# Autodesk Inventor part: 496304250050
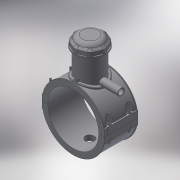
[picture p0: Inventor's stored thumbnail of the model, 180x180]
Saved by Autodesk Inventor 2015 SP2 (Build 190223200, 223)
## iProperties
Created: 2017-07
Part Number: 496304250050
Material: Generic
Description: PLASSON TAPPING SADDLE 250x50
Document SubType Name: Modeling
Designer: KIM
Mass: 1980.45 g
Surface Area: 3874.13 cm^2
Volume: 1980.45 cm^3
Density: 1 g/cm^3
Appearance: Default
Author: KIM
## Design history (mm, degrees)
derived "496304.ipt"
feature "Solid1::496304.ipt"
feature "Solid2::496304.ipt"
feature "Solid4::496304.ipt"
feature "Solid5::496304.ipt"
tag "TaggingFeature1" dims "d2" = 327.6
body "Solid1"
body "Solid2"
other parameters: "d3" = 62.5, "d4" = 176, "d5" = 0, "d6" = 0.1, "d8" = 0, "d19" = 6, "d20" = 6, "d21" = 105.6, "d23" = 0, "d24" = 52.8, "d26" = 0, "d29" = 3, "d30" = 83.33333, "d31" = 6, "d32" = 0, "d33" = 0, "d34" = 0.6, "d40" = 148.2, "d43" = 0, "d45" = 0, "d47" = 248.1, "d70" = 15, "d72" = 0, "d73" = 6, "d75" = 5, "d76" = 0, "d77" = 12.5, "d78" = 155, "d79" = 15, "d80" = 70.4, "d82" = 5 deg, "d84" = 4, "d85" = 14, "d86" = 0, "d87" = 3, "d88" = 0, "d89" = 1, "d90" = 1, "d91" = 140.8, "d92" = 0, "d93" = 0.5, "d94" = 131.57895, "d96" = 290.7, "d97" = 3.52, "d98" = 0, "d102" = 2.5, "d120" = 140 deg, "d121" = 24.228, "d122" = 20 deg, "d124" = 171, "d126" = 0, "d143" = 257.5, "d145" = 26.92308, "d149" = 3.75, "d150" = 29.61538, "d153" = 176, "d154" = 0, "d156" = 142.5, "d157" = 160 deg, "d159" = 7, "d161" = 3.75, "d162" = 105.6, "d163" = 0, "d164" = 125, "d167" = 25, "d168" = 139.02439, "d170" = 3.75, "d172" = 0, "d173" = 1, "d175" = 125, "d176" = 20 deg, "d177" = 17.5, "d178" = 35, "d180" = 0, "d183" = 14, "d184" = 14, "d185" = 57.2, "d186" = 57.2, "d187" = 142.5, "d188" = 10.5, "d189" = 17.5, "d190" = 0, "d191" = 213.75, "d193" = 7, "d194" = 6.16, "d195" = 90 deg, "d197" = 0, "d199" = 0, "d200" = 17.5, "d202" = 0, "d203" = 177, "d204" = 95, "d206" = 85, "d207" = 132.75, "d208" = 138.06, "d209" = 164.61, "d210" = 86, "d213" = 35.1, "d216" = 0, "d217" = 25, "d218" = 25, "d219" = 5, "d224" = 0, "d230" = 5, "d233" = 6, "d236" = 126, "d237" = 52.8, "d238" = 6.02433, "d240" = 52.8, "d241" = 52.8, "d242" = 52.8, "d243" = 6, "d244" = 52.8, "d245" = 52.8, "d246" = 52.8, "d247" = 6, "d248" = 6, "d249" = 6, "d251" = 52.8, "d253" = 6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
